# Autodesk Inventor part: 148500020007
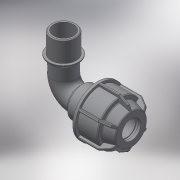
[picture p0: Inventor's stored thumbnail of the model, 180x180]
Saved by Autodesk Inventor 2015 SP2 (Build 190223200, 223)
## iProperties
Created: 2017-08
Part Number: 148500020007
Material: Generic
Description: PLASSON L.14 90° ELBOW MALE ADAPTOR (SILVER) 20-3/4"
Document SubType Name: Modeling
Designer: KIM
Density: 1 g/cm^3
Appearance: Default
Author: KIM
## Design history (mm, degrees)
derived "148500.ipt"
feature "Solid1::148500.ipt"
feature "Solid2::148500.ipt"
tag "TaggingFeature1"
body "Solid1"
body "Solid2"
other parameters: "d2" = 43, "d4" = 15 deg, "d5" = 28.38, "d6" = 9.3654, "d10" = 42, "d16" = 20.4, "d17" = 2.15, "d22" = 32, "d24" = 2.15, "d25" = 37.8, "d26" = 31.5, "d27" = 2.15, "d28" = 135 deg, "d29" = 1.29, "d31" = 1, "d46" = 150 deg, "d49" = 2.1, "d50" = 0, "d58" = 0.6, "d61" = 360 deg, "d63" = 18.6, "d94" = 45, "d96" = 29.0851, "d97" = 18, "d98" = 18.5087, "d99" = 24.72234, "d100" = 135 deg, "d108" = 1, "d112" = 23.4, "d113" = 57, "d114" = 43.86, "d115" = 24.72234, "d116" = 45 deg, "d117" = 0, "d118" = 0, "d119" = 26.441, "d120" = 18, "d121" = 31.7292, "d122" = 18.9, "d123" = 1, "R_" = 26.441, "E_" = 42, "A_" = 57, "l_" = 43, "l_2" = 18, "A_1" = 45
